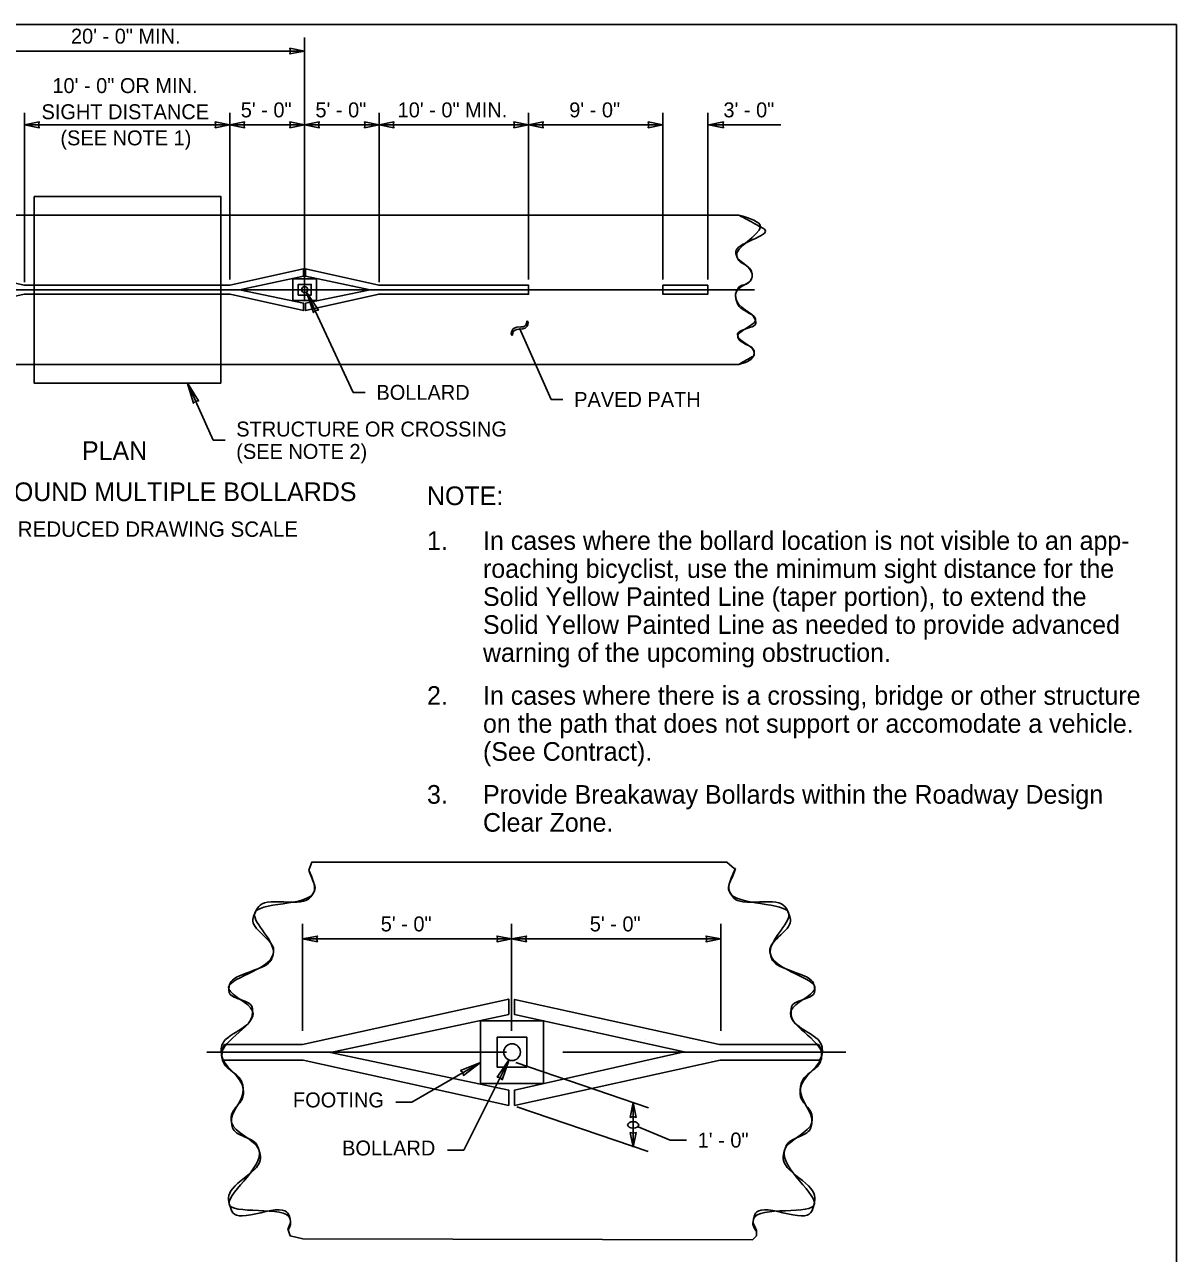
# Model space of a CAD drawing. Extents: x 99862 to 103151, y 100000 to 102076.
# Drawn here: x 101917 to 103151, y 100759 to 102076 of the extents above; entities that cross this region are included whole.
import ezdxf

# ---------------------------------------------------------------- set-up
doc = ezdxf.new("R2010")
doc.units = 0
for name, color, linetype in [('Level 1', 7, 'Continuous'), ('Level 10', 7, 'Continuous'), ('Level 15', 7, 'Continuous'), ('Level 2', 7, 'Continuous'), ('Level 20', 7, 'Continuous'), ('Level 22', 7, 'Continuous'), ('Level 3', 7, 'Continuous'), ('Level 4', 7, 'Continuous'), ('Level 60', 7, 'Continuous'), ('Level 8', 7, 'Continuous')]:
    doc.layers.add(name, color=color, linetype=linetype)

msp = doc.modelspace()

# ---------------------------------------------------------------- linework, layer by layer
at = {"layer": 'Level 1'}
for points in [[(99862, 99999.5), (103151, 99999.5), (103151, 102075.5), (99862, 102075.5)], [(102405.2, 101008.1), (102472.9, 101008.1), (102472.9, 100940.8), (102405.2, 100940.8)], [(102423.1, 100990.4), (102455.1, 100990.4), (102455.1, 100958.4), (102423.1, 100958.4)]]:
    msp.add_lwpolyline(points, close=True, dxfattribs=at)
for points in [[(102678.5, 101171.1), (102677.2, 101171.1), (102669.2, 101178), (102224.7, 101178), (102221.2, 101169.3)], [(102405.2, 101008.1), (102405.2, 100940.8), (102472.9, 100940.8), (102472.9, 101008.1), (102405.2, 101008.1)], [(102423.1, 100958.4), (102423.1, 100990.4), (102455.1, 100990.4), (102455.1, 100958.4), (102423.1, 100958.4)], [(102198.9, 100785.2), (102201.3, 100777.7), (102215, 100774.3), (102696.6, 100773.2)], [(102696.6, 100773.2), (102701.1, 100777.7), (102701.1, 100783.4)]]:
    msp.add_lwpolyline(points, dxfattribs=at)
msp.add_circle((102439.1, 100974.4), 8.94, dxfattribs=at)
for points in [[(102221.2, 101169.3), (102227.1, 101146.5), (102163.2, 101122.4), (102183.1, 101079.3), (102135.6, 101041.8), (102161, 101018.6), (102127.8, 100971.8), (102151.1, 100934.7), (102138.5, 100899.2), (102168, 100869.4), (102136.7, 100809.9), (102201.7, 100792.6), (102198.9, 100785.2)], [(102701.1, 100783.4), (102697.4, 100792.6), (102762.3, 100809.9), (102731.1, 100869.4), (102760.5, 100899.2), (102748, 100934.7), (102771.2, 100971.8), (102738, 101018.6), (102763.4, 101041.8), (102716, 101079.3), (102735.8, 101122.4), (102672, 101146.5), (102678.5, 101171.1)]]:
    msp.add_spline(points, degree=3, dxfattribs=at)
at = {"layer": 'Level 10'}
msp.add_lwpolyline([(101926.9, 101891.4), (102126.9, 101891.4), (102126.9, 101691.4), (101926.9, 101691.4)], close=True, dxfattribs=at)
at = {"layer": 'Level 15'}
for p, q in [((102216.8, 102061.5), (102216.8, 101780.5)), ((101836.8, 102047.1), (102216.8, 102047.1)), ((101916.8, 101980.9), (101916.8, 101799.6)), ((102136.8, 101980.9), (102136.8, 101802.3)), ((102296.8, 101980.9), (102296.8, 101802.3)), ((102456.8, 101980.9), (102456.8, 101802.3)), ((102600.8, 101980.9), (102600.8, 101802.3)), ((102648.8, 101980.9), (102648.8, 101802.3)), ((101916.8, 101968.1), (102136.8, 101968.1)), ((102136.8, 101968.1), (102216.8, 101968.1)), ((102136.8, 101968.1), (102136.8, 101856.6)), ((102216.8, 101968.1), (102296.8, 101968.1)), ((102296.8, 101968.1), (102456.8, 101968.1)), ((102456.8, 101968.1), (102600.8, 101968.1)), ((102727, 101968.1), (102649.9, 101968.1)), ((102296.8, 101834.8), (102296.8, 101799.6)), ((101358.6, 101791.4), (102698.9, 101791.4)), ((102047.2, 101791.4), (102259.2, 101791.4)), ((102218.7, 101788.6), (102269, 101681.4)), ((102438.2, 101744.1), (102438.5, 101746.1)), ((102438.5, 101746.1), (102439.1, 101747.8)), ((102439.1, 101747.8), (102440.1, 101749.2)), ((102440.4, 101746.3), (102439.8, 101744.7)), ((102440.1, 101749.2), (102441.5, 101750.2)), ((102441.2, 101747.4), (102440.4, 101746.3)), ((102442.3, 101748.2), (102441.2, 101747.4)), ((102441.5, 101750.2), (102444.1, 101751.2)), ((102444.1, 101748.8), (102442.3, 101748.2)), ((102444.1, 101751.2), (102448.5, 101751.5)), ((102446.6, 101749.1), (102444.1, 101748.8)), ((102450.7, 101749.3), (102446.6, 101749.1)), ((102447.2, 101750.2), (102480.9, 101673.8)), ((102448.5, 101751.5), (102450.9, 101751.7)), ((102453, 101750.2), (102450.7, 101749.3)), ((102450.9, 101751.7), (102452.3, 101752.3)), ((102452.3, 101752.3), (102453.4, 101753.2)), ((102454.3, 101751.2), (102453, 101750.2)), ((102453.4, 101753.2), (102454.3, 101754.6)), ((102454.3, 101754.6), (102455.2, 101758.1)), ((102455.3, 101752.5), (102454.3, 101751.2)), ((102455.2, 101758.1), (102456.3, 101756.3)), ((102455.9, 101754.2), (102455.3, 101752.5)), ((102456.3, 101756.3), (102455.9, 101754.2)), ((102439.3, 101742.3), (102438.2, 101744.1)), ((102439.8, 101744.7), (102439.3, 101742.3)), ((102091.9, 101689.9), (102118.8, 101630.1)), ((102281.8, 101681.4), (102269, 101681.4)), ((102493.7, 101673.8), (102480.9, 101673.8)), ((102131.6, 101630.1), (102118.8, 101630.1)), ((102214.7, 101111.8), (102214.7, 100997.1)), ((102438.7, 101111.8), (102438.7, 100997.1)), ((102662.7, 101111.8), (102662.7, 100997.1)), ((102214.7, 101095.8), (102438.7, 101095.8)), ((102438.7, 101095.8), (102662.7, 101095.8)), ((102112, 100974.3), (102433.2, 100974.3)), ((102493.6, 100974.3), (102796.6, 100974.3)), ((102405.2, 100963.4), (102331.9, 100920.8)), ((102436.2, 100966.6), (102387.3, 100869.4)), ((102585.5, 100914.8), (102443.3, 100963.3)), ((102331.9, 100920.8), (102314.5, 100920.8)), ((102568.9, 100920.3), (102568.9, 100872.5)), ((102584.8, 100867.8), (102444.1, 100915.7)), ((102574.1, 100894.4), (102608.6, 100880.2)), ((102626, 100880.2), (102608.6, 100880.2)), ((102387.3, 100869.4), (102369.9, 100869.4))]:
    msp.add_line(p, q, dxfattribs=at)
for points in [[(102216.8, 102047.1), (102201.1, 102044), (102201.8, 102047.1), (102201.1, 102050.1)], [(101916.8, 101968.1), (101932.5, 101965), (101931.8, 101968.1), (101932.5, 101971.2)], [(102136.8, 101968.1), (102121.1, 101965), (102121.8, 101968.1), (102121.1, 101971.2)], [(102136.8, 101968.1), (102152.5, 101965), (102151.8, 101968.1), (102152.5, 101971.2)], [(102216.8, 101968.1), (102201.1, 101965), (102201.8, 101968.1), (102201.1, 101971.2)], [(102216.8, 101968.1), (102232.5, 101965), (102231.8, 101968.1), (102232.5, 101971.2)], [(102296.8, 101968.1), (102281.1, 101965), (102281.8, 101968.1), (102281.1, 101971.2)], [(102296.8, 101968.1), (102312.5, 101965), (102311.8, 101968.1), (102312.5, 101971.2)], [(102456.8, 101968.1), (102441.1, 101965), (102441.8, 101968.1), (102441.1, 101971.2)], [(102456.8, 101968.1), (102472.5, 101965), (102471.8, 101968.1), (102472.5, 101971.2)], [(102600.8, 101968.1), (102585.1, 101965), (102585.8, 101968.1), (102585.1, 101971.2)], [(102649.9, 101968.1), (102665.6, 101965), (102664.9, 101968.1), (102665.6, 101971.2)], [(102218.7, 101788.6), (102226.3, 101766.9), (102228.5, 101769.2), (102231.7, 101769.6)], [(102091.1, 101691.8), (102097.7, 101669.8), (102100, 101671.9), (102103.2, 101672.2)], [(102214.7, 101095.8), (102230.5, 101092.7), (102229.7, 101095.8), (102230.5, 101098.8)], [(102438.7, 101095.8), (102423, 101092.7), (102423.7, 101095.8), (102423, 101098.8)], [(102438.7, 101095.8), (102454.5, 101092.7), (102453.7, 101095.8), (102454.5, 101098.8)], [(102662.7, 101095.8), (102647, 101092.7), (102647.7, 101095.8), (102647, 101098.8)], [(102405.2, 100963.4), (102384, 100954.6), (102386.4, 100952.5), (102387, 100949.4)], [(102436.2, 100966.6), (102423.3, 100947.6), (102426.4, 100947.2), (102428.6, 100944.9)], [(102568.9, 100920.3), (102565.8, 100904.5), (102568.9, 100905.3), (102572, 100904.5)], [(102568.9, 100872.5), (102565.8, 100888.2), (102568.9, 100887.5), (102572, 100888.2)]]:
    msp.add_lwpolyline(points, close=True, dxfattribs=at)
msp.add_ellipse((102568.9, 100896.4), major_axis=(-6, 0), ratio=0.57735, dxfattribs=at)
at = {"layer": 'Level 2'}
for p, q in [((102682, 101871.4), (101373.2, 101871.4)), ((101722.2, 101871.4), (102238.5, 101871.4)), ((101373.2, 101711.4), (102682, 101711.4))]:
    msp.add_line(p, q, dxfattribs=at)
for points in [[(102682, 101871.4), (102238.5, 101871.4), (101722.2, 101871.4)], [(101373.2, 101711.4), (102682, 101711.4)], [(102678.5, 101171.1), (102677.2, 101171.1), (102669.2, 101178), (102224.7, 101178), (102221.2, 101169.3)], [(102199.2, 100784), (102201.3, 100777.7), (102215, 100774.3), (102696.6, 100773.2)], [(102696.6, 100773.2), (102701.1, 100777.7), (102701.1, 100782.1)]]:
    msp.add_lwpolyline(points, dxfattribs=at)
msp.add_spline([(102682, 101711.4), (102697.7, 101720.2), (102698.6, 101723.5), (102680.9, 101741.5), (102700, 101758.1), (102679.8, 101779.1), (102679.8, 101790.1), (102695.8, 101803.4), (102695.8, 101810.1), (102679.8, 101827.2), (102705.3, 101858.7), (102682, 101871.4)], degree=3, dxfattribs=at)
for points in [[(102682, 101711.4), (102687.2, 101714.4), (102692.5, 101717.3), (102697.7, 101720.2), (102698.7, 101720.8), (102698.6, 101722.7), (102698.6, 101723.5), (102698.2, 101729.7), (102681.9, 101735.9), (102680.9, 101741.5), (102679.8, 101747.1), (102701.9, 101752.4), (102700, 101758.1), (102697.8, 101764.6), (102682.1, 101771.7), (102679.8, 101779.1), (102678.9, 101781.9), (102678.4, 101787), (102679.8, 101790.1), (102682.3, 101796), (102693.3, 101797.6), (102695.8, 101803.4), (102696.6, 101805.3), (102696.4, 101808.4), (102695.8, 101810.1), (102693.8, 101816), (102681.9, 101821.3), (102679.8, 101827.2), (102676.1, 101837.4), (102717.2, 101852.2), (102705.3, 101858.7), (102697.5, 101863), (102689.8, 101867.2), (102682, 101871.4)], [(102221.2, 101169.3), (102224.3, 101160.8), (102229.5, 101151), (102227.1, 101146.5), (102219.2, 101131.8), (102170.2, 101139.1), (102163.2, 101122.4), (102158.4, 101110.8), (102185.4, 101089.5), (102183.1, 101079.3), (102180.1, 101066.3), (102136.8, 101055), (102135.6, 101041.8), (102135, 101034.3), (102161.3, 101027.4), (102161, 101018.6), (102160.6, 101004), (102126.1, 100987.8), (102127.8, 100971.8), (102129.2, 100959.6), (102149.9, 100947.2), (102151.1, 100934.7), (102152.1, 100923.9), (102137.2, 100910), (102138.5, 100899.2), (102140, 100887.2), (102165, 100880), (102168, 100869.4), (102172.7, 100852.4), (102132.3, 100826.9), (102136.7, 100809.9), (102141.2, 100793), (102198.6, 100811.9), (102201.7, 100792.6), (102202.1, 100789.9), (102201, 100787), (102199.2, 100784)], [(102701.1, 100782.1), (102698.6, 100785.7), (102696.9, 100789.3), (102697.4, 100792.6), (102700.5, 100811.9), (102757.9, 100793), (102762.3, 100809.9), (102766.8, 100826.9), (102726.3, 100852.4), (102731.1, 100869.4), (102734, 100880), (102759, 100887.2), (102760.5, 100899.2), (102761.9, 100910), (102746.9, 100923.9), (102748, 100934.7), (102749.2, 100947.2), (102769.9, 100959.6), (102771.2, 100971.8), (102773, 100987.8), (102738.5, 101004), (102738, 101018.6), (102737.8, 101027.4), (102764.1, 101034.3), (102763.4, 101041.8), (102762.3, 101055), (102718.9, 101066.3), (102716, 101079.3), (102713.6, 101089.5), (102740.7, 101110.8), (102735.8, 101122.4), (102728.9, 101139.1), (102679.9, 101131.8), (102672, 101146.5), (102669.4, 101151.3), (102675.5, 101162.1), (102678.5, 101171.1)]]:
    msp.add_open_spline(points, degree=3, dxfattribs=at)
at = {"layer": 'Level 22'}
for p, q in [((101916.3, 101796.2), (102136.7, 101796.2)), ((101916.5, 101786.6), (102137, 101786.6)), ((102165.4, 101796.2), (102165.4, 101796.2)), ((102165.6, 101786.6), (102165.6, 101786.6)), ((102268.1, 101796.2), (102268.1, 101796.2)), ((102268.3, 101786.6), (102268.3, 101786.6)), ((102456.8, 101796.2), (102456.8, 101786.6)), ((102294.6, 100987.7), (102294.6, 100987.7)), ((102582.4, 100987.7), (102582.4, 100987.7)), ((102295.5, 100960.8), (102295.5, 100960.8)), ((102403.6, 100962.2), (102403.6, 100962.2)), ((102583, 100960.8), (102583, 100960.8))]:
    msp.add_line(p, q, dxfattribs=at)
msp.add_lwpolyline([(102217.9, 101777), (102217.9, 101769.1), (102296.8, 101786.7), (102296.1, 101786.7)], dxfattribs=at)
for centre, radius in [((102216.9, 101791.5), 3.19), ((102439.1, 100974.4), 8.94)]:
    msp.add_circle(centre, radius, dxfattribs=at)
at = {"layer": 'Level 3'}
for centre, radius, start, end in [((102216.9, 101791.5), 3.19, 0, 180), ((102216.9, 101791.5), 3.19, 180, 0), ((102439.1, 100974.4), 8.94, 0, 180), ((102439.1, 100974.4), 8.94, 180, 0)]:
    msp.add_arc(centre, radius, start, end, dxfattribs=at)
at = {"layer": 'Level 4'}
msp.add_lwpolyline([(102210.1, 101785.6), (102224, 101785.6), (102224, 101797.1), (102210.1, 101797.1)], close=True, dxfattribs=at)
at = {"layer": 'Level 60'}
msp.add_line((103151, 102075.5), (103151, 102075.5), dxfattribs=at)
at = {"layer": 'Level 8'}
for p, q in [((102217.9, 101805.8), (102287.2, 101791.4)), ((102287.2, 101791.4), (102217.9, 101777))]:
    msp.add_line(p, q, dxfattribs=at)
for points in [[(102146.9, 101791.4), (102215.7, 101805.9), (102215.7, 101813.8), (102136.7, 101796.2), (101916.3, 101796.2), (101838.2, 101813.8), (101838.1, 101805.8), (101907, 101791.4), (101837.9, 101777), (101837.9, 101769.1), (101916.5, 101786.6), (102137, 101786.6), (102215.7, 101769.1), (102215.7, 101777)], [(102204.3, 101803), (102229.5, 101803), (102229.5, 101779.9), (102204.3, 101779.9)]]:
    msp.add_lwpolyline(points, close=True, dxfattribs=at)
for points in [[(102217.9, 101777), (102217.9, 101769.1), (102296.5, 101786.6), (102456.8, 101786.6), (102456.8, 101796.2), (102296.3, 101796.2), (102217.9, 101813.7), (102217.9, 101805.8)], [(102600.8, 101796.2), (102600.8, 101786.6), (102648.8, 101786.6), (102648.8, 101796.2), (102600.8, 101796.2)], [(102600.8, 101786.6), (102648.8, 101786.6), (102648.8, 101796.2), (102600.8, 101796.2), (102600.8, 101786.6)], [(102244.6, 100974.1), (102435.6, 101014.9), (102435.6, 101031.3), (102214.5, 100982.7), (102131, 100982.7)], [(102767.4, 100982.7), (102661.5, 100982.7), (102441.8, 101031), (102441.8, 101014.6), (102623.6, 100974.6), (102441.8, 100933.8), (102441.8, 100917.4)], [(102131, 100982.7), (102128.7, 100977.8), (102128.2, 100970.2), (102129.5, 100965.8)], [(102768.7, 100965.8), (102770.6, 100970.2), (102770.2, 100977.7), (102767.4, 100982.7)], [(102129.5, 100965.8), (102215.4, 100965.8), (102435.6, 100917.4), (102435.6, 100933.8), (102244.6, 100974.1)], [(102441.8, 100917.4), (102662, 100965.8), (102768.7, 100965.8)]]:
    msp.add_lwpolyline(points, dxfattribs=at)

# ---------------------------------------------------------------- texts
at = {"layer": 'Level 20'}
for s, height, p in [('20\' - 0" MIN.', 16, (101966.5, 102055.1)), ('10\' - 0" OR MIN.', 16, (101946.6, 102002.1)), (' SIGHT DISTANCE ', 16, (101929, 101974.1)), ('5\' - 0"', 16, (102148.4, 101976.1)), ('5\' - 0"', 16, (102228.4, 101976.1)), ('10\' - 0" MIN.', 16, (102316.5, 101976.1)), ('9\' - 0"', 16, (102500.4, 101976.1)), ('3\' - 0"', 16, (102665.6, 101976.1)), ('(SEE NOTE 1)', 16, (101955.2, 101946.1)), ('STRUCTURE OR CROSSING', 16, (102143.6, 101634.1)), ('PLAN', 20, (101978.3, 101608.9)), ('(SEE NOTE 2)', 16, (102143.6, 101610.1)), ('MARKING AROUND MULTIPLE BOLLARDS', 20, (101735.9, 101564.9)), ('NOTE:', 20, (102348, 101560.6)), ('SHOWN AT REDUCED DRAWING SCALE', 16.5, (101784.4, 101526.6)), ('1.', 20, (102348, 101512.6)), ('In cases where the bollard location is not visible to an app-', 20, (102408, 101512.6)), ('roaching bicyclist, use the minimum sight distance for the ', 20, (102408, 101482.6)), ('Solid Yellow Painted Line (taper portion), to extend the ', 20, (102408, 101452.6)), ('Solid Yellow Painted Line as needed to provide advanced ', 20, (102408, 101422.6)), ('warning of the upcoming obstruction.', 20, (102408, 101392.6)), ('2.', 20, (102348, 101346.6)), ('In cases where there is a crossing, bridge or other structure', 20, (102408, 101346.6)), ('on the path that does not support or accomodate a vehicle. ', 20, (102408, 101316.6)), ('(See Contract).', 20, (102408, 101286.6)), ('3.', 20, (102348, 101240.6)), ('Provide Breakaway Bollards within the Roadway Design ', 20, (102408, 101240.6)), ('Clear Zone.', 20, (102408, 101210.6)), ('5\' - 0"', 16, (102298.4, 101103.8)), ('5\' - 0"', 16, (102522.4, 101103.8)), ('FOOTING', 16, (102204.4, 100915.2)), ('BOLLARD', 16, (102257, 100863.7)), ('1\' - 0"', 16, (102638, 100872.2))]:
    msp.add_text(s, height=height, dxfattribs=at).set_placement(p)
for s, p in [('BOLLARD', (102293.8, 101673.4)), ('PAVED PATH', (102505.7, 101665.8))]:
    msp.add_text(s, height=16, rotation=360, dxfattribs=at).set_placement(p)

doc.saveas('drawing.dxf')
